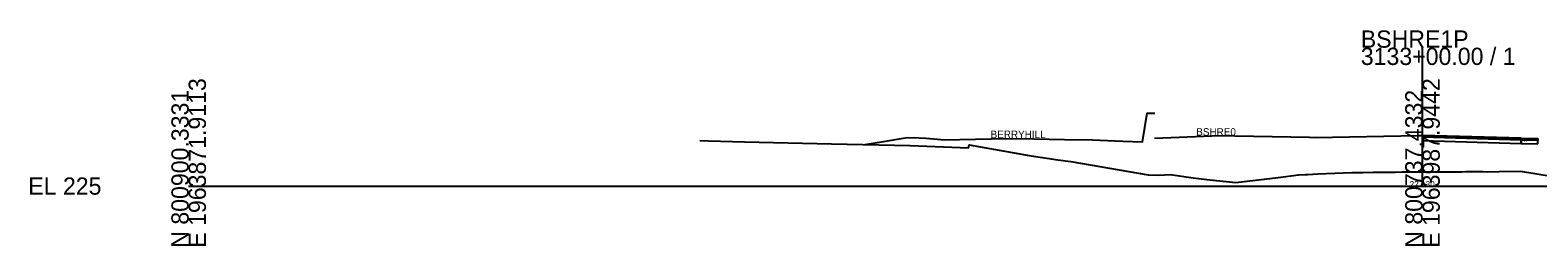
# Model space of a CAD drawing. Extents: x -26 to 403, y -10 to 6039.
# Drawn here: x -25.7 to 218.7, y 4490.3 to 4525.3 of the extents above; entities that cross this region are included whole.
import ezdxf

# ---------------------------------------------------------------- set-up
doc = ezdxf.new("R2010")
doc.units = 0
for name, color, linetype in [('Default', 7, 'Continuous'), ('RD_GPK_XS_Cell', 7, 'Continuous'), ('RD_TX_Misc1', 7, 'Continuous'), ('RD_XS_Base', 7, 'Continuous'), ('RD_XS_ExGround', 7, 'Continuous'), ('RD_XS_Pave', 7, 'Continuous'), ('RD_XS_PaveOvlay', 7, 'Continuous'), ('RD_XS_TX_Elev_EX', 7, 'Continuous')]:
    doc.layers.add(name, color=color, linetype=linetype)

msp = doc.modelspace()

# ---------------------------------------------------------------- linework, layer by layer
at = {"layer": 'RD_GPK_XS_Cell'}
for p, q in [((200, 4500), (200, 4522.43)), ((0, 4500), (200, 4500)), ((200, 4500), (400, 4500))]:
    msp.add_line(p, q, dxfattribs=at)
at = {"layer": 'RD_XS_Base'}
for points in [[(216, 4507.42), (200, 4507.9)], [(200, 4507.9), (200, 4507.4)], [(200, 4507.4), (216, 4506.92)], [(216, 4507.42), (216, 4506.92)], [(218.7, 4507.37), (216, 4507.42)], [(216, 4506.92), (216, 4507.42)], [(216, 4506.92), (218.7, 4506.87)], [(218.7, 4506.87), (218.7, 4507.37)]]:
    msp.add_lwpolyline(points, dxfattribs=at)
at = {"layer": 'RD_XS_ExGround'}
msp.add_lwpolyline([(82.85, 4507.37), (84.28, 4507.31), (90.08, 4507.17), (104.18, 4506.87), (116.93, 4506.56), (126.4, 4506.21), (126.53, 4506.66), (136.23, 4504.96), (140.9, 4504.27), (143, 4503.98), (155.53, 4501.83), (157.28, 4501.78), (159.11, 4501.88), (162.85, 4501.32), (165.04, 4501.07), (169.77, 4500.57), (176.62, 4501.41), (179.9, 4501.83), (181.06, 4501.88), (181.44, 4501.89), (183.04, 4501.96), (188.54, 4502.18), (189.23, 4502.21), (190.35, 4502.22), (192, 4502.24), (192.37, 4502.24), (194.78, 4502.27), (195.55, 4502.27), (196.64, 4502.28), (197.84, 4502.28), (198.21, 4502.28), (199.64, 4502.3), (200, 4502.3), (201, 4502.31), (203.91, 4502.33), (205.32, 4502.33), (206.3, 4502.33), (206.97, 4502.34), (209.79, 4502.34), (210.5, 4502.33), (212.42, 4502.37), (215.89, 4502.42), (223.5, 4501.16)], dxfattribs=at)
at = {"layer": 'RD_XS_Pave'}
for points in [[(109.61, 4506.75), (112.63, 4507.25), (116.47, 4507.89), (118.41, 4507.82), (119.48, 4507.79), (121.41, 4507.59), (122.48, 4507.49), (130.09, 4507.63), (134.5, 4507.72), (141.96, 4507.57), (146.52, 4507.47), (151.41, 4507.28), (154.61, 4507.15), (155.36, 4511.82), (156.12, 4511.82), (156.62, 4511.82)], [(156.57, 4507.76), (165.84, 4508.15), (166.58, 4508.18), (181.71, 4507.9), (182.6, 4507.88), (199.31, 4508.2), (200, 4508.21)], [(200, 4507.9), (200, 4508.06)], [(200, 4508.06), (216, 4507.58)], [(216, 4507.42), (200, 4507.9)], [(216, 4507.58), (216, 4507.42)], [(216, 4507.58), (218.7, 4507.54)], [(216, 4507.42), (216, 4507.58)], [(218.7, 4507.37), (216, 4507.42)], [(218.7, 4507.54), (218.7, 4507.37)]]:
    msp.add_lwpolyline(points, dxfattribs=at)
at = {"layer": 'RD_XS_PaveOvlay'}
for points in [[(216, 4507.74), (200, 4508.22)], [(200, 4508.22), (200, 4508.06)], [(200, 4508.06), (216, 4507.58)], [(216, 4507.58), (216, 4507.74)], [(216, 4507.74), (218.7, 4507.7)], [(216, 4507.58), (216, 4507.74)], [(218.7, 4507.54), (216, 4507.58)], [(218.7, 4507.7), (218.7, 4507.54)]]:
    msp.add_lwpolyline(points, dxfattribs=at)

# ---------------------------------------------------------------- texts
at = {"layer": 'Default'}
for s, height, p in [('CL', 0.208, (200, 4508.01)), ('CL1', 0.208, (200, 4507.85)), ('CL2', 0.208, (200, 4507.69)), ('CL3', 0.208, (200, 4507.19)), ('Exterior Boundary', 0.2083, (200, 4508.01)), ('R_EP', 0.208, (216, 4507.53)), ('R_EP1', 0.208, (216, 4507.37)), ('R_EP2', 0.208, (216, 4507.21)), ('R_EP3', 0.208, (216, 4506.71)), ('-', 0.0001, (0, 4500))]:
    msp.add_text(s, height=height, dxfattribs=at).set_placement(p)
at = {"layer": 'RD_GPK_XS_Cell'}
for s, p in [('BSHRE1P', (190, 4522.43)), ('3133+00.00 / 1', (190, 4519.63)), ('EL 225', (-26, 4498.6))]:
    msp.add_text(s, height=2.8, dxfattribs=at).set_placement(p)
for s, p in [('E 1963871.9113', (2.8, 4490)), ('E 1963987.9442', (202.8, 4490)), ('N 800900.3331', (0, 4490)), ('N 800737.4332', (200, 4490))]:
    msp.add_text(s, height=2.8, rotation=90, dxfattribs=at).set_placement(p)
at = {"layer": 'RD_TX_Misc1'}
for s, p in [('BSHRE0', (163.33, 4508.18)), ('BERRYHILL', (129.99, 4507.78))]:
    msp.add_text(s, height=1.2, dxfattribs=at).set_placement(p)
at = {"layer": 'RD_XS_TX_Elev_EX'}
msp.add_text('227.30', height=1, dxfattribs=at).set_placement((197.9, 4499.8))

doc.saveas('drawing.dxf')
